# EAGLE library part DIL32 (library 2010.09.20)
Dual In Line
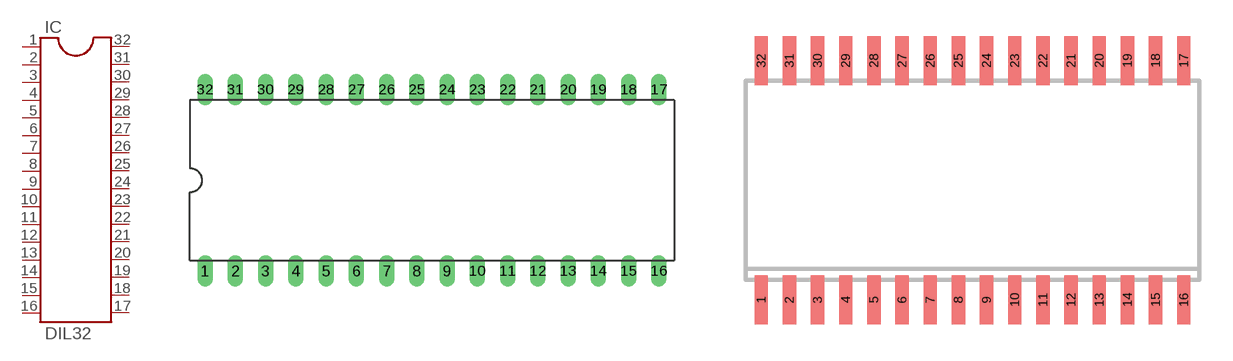
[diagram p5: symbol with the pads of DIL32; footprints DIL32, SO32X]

Designator prefix IC

## DIL32  [DIL32]
1  1  pas
2  2  pas
3  3  pas
4  4  pas
5  5  pas
6  6  pas
7  7  pas
8  8  pas
9  9  pas
10  10  pas
11  11  pas
12  12  pas
13  13  pas
14  14  pas
15  15  pas
16  16  pas
17  17  pas
18  18  pas
19  19  pas
20  20  pas
21  21  pas
22  22  pas
23  23  pas
24  24  pas
25  25  pas
26  26  pas
27  27  pas
28  28  pas
29  29  pas
30  30  pas
31  31  pas
32  32  pas

## DIL32-SOX  [SO32X]
Pads as for DIL32

## DIL32-SOJ/3  [SOJ32/3]
Pads as for DIL32

## DIL32-SOJ/4  [SOJ32/4]
Pads as for DIL32

## DIL32-SOP/4  [SOP32-4]
Pads as for DIL32

## DIL32-TSOP  [TSOP32]
Pads as for DIL32

## Footprint DIL32 (pad centres in mm)
Dual In Line Package
drill 0.813 long: 1 -19.05,-7.62; 2 -16.51,-7.62; 3 -13.97,-7.62; 4 -11.43,-7.62; 5 -8.89,-7.62; 6 -6.35,-7.62; 7 -3.81,-7.62; 8 -1.27,-7.62; 9 1.27,-7.62; 10 3.81,-7.62; 11 6.35,-7.62; 12 8.89,-7.62; 13 11.43,-7.62; 14 13.97,-7.62; 15 16.51,-7.62; 16 19.05,-7.62; 17 19.05,7.62; 18 16.51,7.62; 19 13.97,7.62; 20 11.43,7.62; 21 8.89,7.62; 22 6.35,7.62; 23 3.81,7.62; 24 1.27,7.62; 25 -1.27,7.62; 26 -3.81,7.62; 27 -6.35,7.62; 28 -8.89,7.62; 29 -11.43,7.62; 30 -13.97,7.62; 31 -16.51,7.62; 32 -19.05,7.62

## Footprint SO32X (pad centres in mm)
SMALL OUTLINE INTEGRATED CIRCUIT extra wide body 8.9 mm/JEDEC MO-120AC
smd 0.6 x 2.2: 1 -9.525,-5.4; 2 -8.255,-5.4; 3 -6.985,-5.4; 4 -5.715,-5.4; 5 -4.445,-5.4; 6 -3.175,-5.4; 7 -1.905,-5.4; 8 -0.635,-5.4; 9 0.635,-5.4; 10 1.905,-5.4; 11 3.175,-5.4; 12 4.445,-5.4; 13 5.715,-5.4; 14 6.985,-5.4; 15 8.255,-5.4; 16 9.525,-5.4; 17 9.525,5.4; 18 8.255,5.4; 19 6.985,5.4; 20 5.715,5.4; 21 4.445,5.4; 22 3.175,5.4; 23 1.905,5.4; 24 0.635,5.4; 25 -0.635,5.4; 26 -1.905,5.4; 27 -3.175,5.4; 28 -4.445,5.4; 29 -5.715,5.4; 30 -6.985,5.4; 31 -8.255,5.4; 32 -9.525,5.4

## Footprint SOJ32/3 (pad centres in mm)
Small Outline J-Bend
smd 0.635 x 1.905: 1 -8.89,-3.759; 2 -7.62,-3.759; 3 -6.35,-3.759; 4 -5.08,-3.759; 5 -3.81,-3.759; 6 -2.54,-3.759; 7 -1.27,-3.759; 8 0,-3.759; 9 1.27,-3.759; 10 2.54,-3.759; 11 3.81,-3.759; 12 5.08,-3.759; 13 6.35,-3.759; 14 7.62,-3.759; 15 8.89,-3.759; 16 10.16,-3.759; 17 10.16,3.505; 18 8.89,3.505; 19 7.62,3.505; 20 6.35,3.505; 21 5.08,3.505; 22 3.81,3.505; 23 2.54,3.505; 24 1.27,3.505; 25 0,3.505; 26 -1.27,3.505; 27 -2.54,3.505; 28 -3.81,3.505; 29 -5.08,3.505; 30 -6.35,3.505; 31 -7.62,3.505; 32 -8.89,3.505

## Footprint SOJ32/4 (pad centres in mm)
Small Outline J-Bend
smd 0.635 x 1.905: 1 -8.89,-4.902; 2 -7.62,-4.902; 3 -6.35,-4.902; 4 -5.08,-4.902; 5 -3.81,-4.902; 6 -2.54,-4.902; 7 -1.27,-4.902; 8 0,-4.902; 9 1.27,-4.902; 10 2.54,-4.902; 11 3.81,-4.902; 12 5.08,-4.902; 13 6.35,-4.902; 14 7.62,-4.902; 15 8.89,-4.902; 16 10.16,-4.902; 17 10.16,5.029; 18 8.89,5.029; 19 7.62,5.029; 20 6.35,5.029; 21 5.08,5.029; 22 3.81,5.029; 23 2.54,5.029; 24 1.27,5.029; 25 0,5.029; 26 -1.27,5.029; 27 -2.54,5.029; 28 -3.81,5.029; 29 -5.08,5.029; 30 -6.35,5.029; 31 -7.62,5.029; 32 -8.89,5.029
